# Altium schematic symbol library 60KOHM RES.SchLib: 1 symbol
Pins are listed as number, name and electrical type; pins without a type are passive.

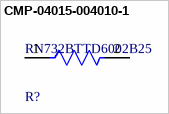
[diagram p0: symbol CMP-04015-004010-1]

## CMP-04015-004010-1
designator R?, comment RN732BTTD6002B25
60kΩ ±0.1% 0.125W, 1/8W Chip Resistor 1206 (3216 Metric) Moisture Resistant Thin Film; Resistance: 60kR; Voltage Rating: 150V; Power Rating: 125mW; Temperature Coefficient: 25ppm/°C
footprint FP-RN732B-IPC_B
footprint FP-RN732B-IPC_C
footprint FP-RN732B-IPC_A
footprint FP-RN732B-MFG
pins: 1, 2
